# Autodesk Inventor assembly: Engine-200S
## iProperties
Created: 2006-01
Part Number: Engine-200S
Document SubType Name: Assembly
Manufacturer: Standard
Standards Organization: Custom
Weld Material: Default
Description: iAssembly of Engine MKII
Designer: Autodesk
Mass: 281.595 g
Surface Area: 1059.89 cm^2
Volume: 67.4779 cm^3
Density: 4.17314 g/cm^3
DriveMe: 0,0 deg
Author: Autodesk
